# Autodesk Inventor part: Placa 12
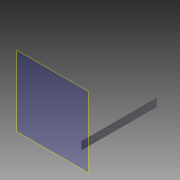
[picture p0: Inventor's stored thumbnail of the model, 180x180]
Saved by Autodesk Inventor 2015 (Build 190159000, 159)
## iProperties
Created: 2015-04
Part Number: Placa 12
Material: Generic
Document SubType Name: Modeling
Designer: suporte
Density: 1 g/cm^3
Appearance: Default
Author: suporte
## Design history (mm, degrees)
workplane "Work Plane1"
sketch "Sketch1"
  geometry: L1 (812.5, 518.558)-(812.5, -400) reference; L2 (830.6, 330)-(825.6, 330) reference; L3 (812.5, 518.558)-(825, 518.558); L4 (825, 518.558)-(825, 317.5); L5 (825, 317.5)-(812.5, 317.5); L6 (812.5, 317.5)-(812.5, 518.558); 1 further point
  constraints: 8 end point, 2 parallel, 1 horizontal, 1 perpendicular
  dimensions: "d0" = 12.5 vertical distance of L2.start L4.end; "d1" = 12.5 distance of L4.end L5.end
extrude "Extrusion1" new body sketch "Sketch1" distance "d2" = 2100; taper "d3" = 0 deg
body "Solid1"
node "Reference1"
node "Reference2"
